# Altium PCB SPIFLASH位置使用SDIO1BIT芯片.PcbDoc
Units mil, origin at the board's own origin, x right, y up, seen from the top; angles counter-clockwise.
Board outline 314.96 x 298.78 mil, 2 copper layers (Top Layer, Bottom Layer), stack 10.4 mil thick; 1 components, 117 nets, 16 pads, 3 vias.
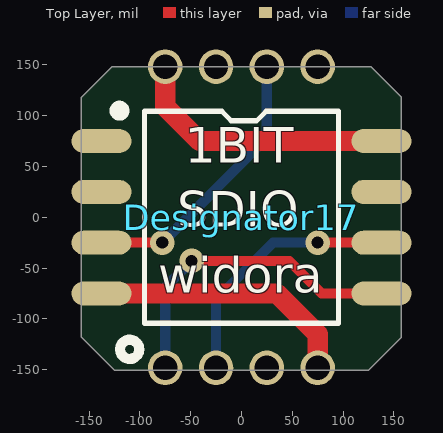
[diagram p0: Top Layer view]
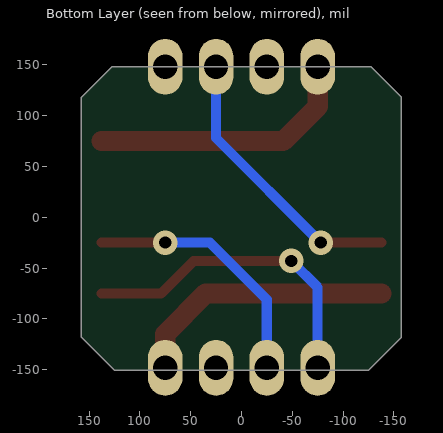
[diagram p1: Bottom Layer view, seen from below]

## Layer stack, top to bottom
Top Layer: signal copper 1.4
Dielectric: core 7.6, FR-4, Dk 4.8
Bottom Layer: signal copper 1.4

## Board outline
-125,-150.59 -157.48,-118.11 -157.48,118.11 -127.4,148.19 127.4,148.19 157.48,118.11 157.48,-118.11 125,-150.59

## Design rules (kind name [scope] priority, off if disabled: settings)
AssemblyTestPointUsage [All] p1 off:
AssemblyTestpoint [All] p1 off: testpointundercomponent=TRUE minsize=40 maxsize=100 preferedsize=60 minholesize=0 maxholesize=40 preferedholesize=32 testpointgrid=1 usegrid=TRUE gridtolerance=0.01 allowsidetop=TRUE allowsidebottom=TRUE
Clearance Clearance_Polygon [InPolygon] p1: gap=6
Clearance [All] p2: gap=4
ComponentClearance [All] p1 off: gap=1 collisioncheckmode=3 verticalgap=1 showdistances=FALSE
DiffPairsRouting [All] p1: maxlimit=20 minlimit=4 mostfreqgap=5 maxuncoupledlength=3000
FabricationTestPointUsage TestPointUsage [All] p1 off: valid=0 allowmultiple=FALSE
FabricationTestpoint Testpoint [(IsPad And (OnTopLayer Or OnBottomLayer))] p1 off: side=3 testpointundercomponent=TRUE minsize=40 maxsize=100 preferedsize=60 minholesize=0 maxholesize=40 preferedholesize=32 testpointgrid=1 allowsidetop=TRUE allowsidebottom=TRUE usegrid=TRUE gridtolerance=0.01
Height [All] p1 off: minheight=0 maxheight=1000 prefheight=500
HoleSize [All] p1: absolutevalues=TRUE maxlimit=150 minlimit=1 maxpercent=80.000 minpercent=20.000
MinimumSolderMaskSliver [All] p1 off: minsoldermaskwidth=1
PlaneClearance [All] p1: clearance=6
PlaneConnect [All] p1: planeconnectstyle=Direct reliefexpansion=20 reliefentries=4 reliefconductorwidth=25 reliefairgap=10
PolygonConnect PolygonConnect_isvia [All vs IsVia] p1: connectstyle=Direct reliefconductorwidth=10 reliefentries=4 polygonreliefangle="90 Angle"
PolygonConnect [All] p2: connectstyle=Direct reliefconductorwidth=8 reliefentries=4 polygonreliefangle="90 Angle"
RoutingVias [All] p1: holewidth=8 width=16 viastyle="Through Hole" minholewidth=8 minwidth=16 maxholewidth=100 maxwidth=100
ShortCircuit [InNet('WIFI') vs InNet('GND')] p1 off: allowed=FALSE
SilkToSilkClearance [All] p1: silktosilkclearance=0
SilkscreenOverComponentPads [IsPad] p1: minsilkscreentomaskgap=0
SolderMaskExpansion [All] p1: expansion=4
Width [All] p1: maxlimit=100 minlimit=4 preferedwidth=5
14 further rules are at their usual default settings.

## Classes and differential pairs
differential pair U: +U_P -U_N

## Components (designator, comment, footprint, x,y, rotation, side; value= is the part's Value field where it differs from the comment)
Designator17 "Comment" SOP8W 0,0 r270 top locked

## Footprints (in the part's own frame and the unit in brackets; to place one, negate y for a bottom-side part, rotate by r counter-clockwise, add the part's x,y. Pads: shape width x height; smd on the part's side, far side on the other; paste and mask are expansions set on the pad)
SOP8W [mil] "Small Outline; 8 Leads; Body Width 7.5 mm; Pitch 1.27 mm"
  oval 23.62x59.06 smd: 1(-75,-137.8) 2(-25,-137.8) 3(25,-137.8) 4(75,-137.8) 5(75,137.8) 6(25,137.8) 7(-25,137.8) 8(-75,137.8)
  silkscreen extent -110,-125 104,95

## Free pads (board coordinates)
  round 34 / inner round 34 / far side oval 34x55 hole 24 mask+2: 1(-75,-148.19) 2(-25,-148.19) 3(25,-148.19) 4(75,-148.19) 5(75,148.19) 6(25,148.19) 7(-25,148.19) 8(-75,148.19)

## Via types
v1: diameter 24, hole 12, Top Layer to Bottom Layer, tented both sides, 3 vias

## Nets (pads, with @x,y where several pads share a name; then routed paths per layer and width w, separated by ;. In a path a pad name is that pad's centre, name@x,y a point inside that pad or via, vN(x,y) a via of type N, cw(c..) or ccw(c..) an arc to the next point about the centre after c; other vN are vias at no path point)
AAGND: 
AGND: 
AVCC: 
AVDD2V8: 
DVP-Y2: 
DVP-Y3: 
DVP-Y4: 
DVP-Y5: 
DVP-Y6: 
DVP-Y7: 
DVP-Y8: 
DVP-Y9: 
DVP_DVDD: 
DVP_HSYNC: 
DVP_PCLK: 
DVP_RST: 
DVP_SCL: 
DVP_SDA: 
DVP_VSYNC: 
DVP_XCLK: 
FMINL: 
FMINR: 
GND: Designator17.4 pad.4 | length 262.6
  Top Layer w20: Designator17.4 35,-75 75,-115 pad.4
HPCOM: 
HPCOMFB: 
HPL: 
HPR: 
LCD_CLK: 
LCD_D3: 
LCD_D4: 
LCD_D5: 
LCD_D6: 
LCD_D7: 
LCD_D10: 
LCD_D11: 
LCD_D12: 
LCD_D13: 
LCD_D14: 
LCD_D15: 
LCD_D19: 
LCD_D20: 
LCD_D21: 
LCD_D22: 
LCD_D23: 
LCD_DE: 
LCD_HSYNC: 
LCD_VSYNC: 
LEDA: 
LEDK: 
LINL: 
LRADC: 
MICIN: 
NetC42_1: 
NetC44_1: 
NetC45_1: 
NetC46_1: 
NetC47_1: 
NetC54_1: 
NetC54_2: 
NetC56_2: 
NetD1_A: 
NetD4_K: 
NetDS1_K: 
NetL1_1: 
NetL2_1: 
NetL3_1: 
NetP1_35: 
NetP1_37: 
NetP1_38: 
NetP1_39: 
NetP1_40: 
NetR8_2: 
NetR10_2: 
NetR12_2: 
NetR25_2: 
NetR32_1: 
NetR38_1: 
NetR39_2: 
NetR41_1: 
NetR42_2: 
OUT+: 
OUT-: 
PA0: 
PA1: 
PA2: 
PA3: 
PE12: 
RSTN: 
SDC0_CLK: Designator17.3 pad.6 | length 275.7
  Top Layer w10: Designator17.3 v1(-78,-25)
  Bottom Layer w10: v1(-78,-25) 25,78 pad.6
SDC0_CMD: Designator17.5 pad.1 | length 316
  Top Layer w10: v1(-49,-43) 47,-43 79,-75 Designator17.5
  Bottom Layer w10: pad.1 -75,-69 v1(-49,-43)
SDC0_D0: Designator17.6 pad.2 | length 253.2
  Top Layer w10: v1(75,-25) Designator17.6
  Bottom Layer w10: pad.2 -25,-81 31,-25 v1(75,-25)
SDC0_D1: 
SDC0_D2: 
SDC0_D3: 
SPI0_CLK: 
SPI0_CS: 
SPI0_MISO: 
SPI0_MOSI: pad.5
SVREF: 
TV_IN0: 
TV_OUT: 
TV_VRN: 
TV_VRP: 
U_N: 
U_P: 
USB_DM: 
USB_DP: 
V5V: 
VCC3V3: Designator17.8 pad.8 | length 266.1
  Top Layer w20: pad.8 -75,109 -41,75 Designator17.8
VCC_CORE: 
VCC_DRAM: 
VCC_TV: 
VCCIN: 
VRA1: 
VRA2: 
XI: 
XO: 
pads on no net: Designator17.1 Designator17.2 Designator17.7

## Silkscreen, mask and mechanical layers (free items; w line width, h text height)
Top Overlay:
  circle w10: c-110,-130 r9.43
  text "1BIT" at -56,42 h60
  text "SDIO" at -63,-21 h60
  text "widora" at -82,-86 h60
Mechanical 1:
  lines w5: -157.48,-118.11 -157.48,118.11 -127.4,148.19 -75,148.19 127.4,148.19 157.48,118.11 157.48,-118.11 125,-150.59 -72.6,-150.59 -125,-150.59 -157.48,-118.11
